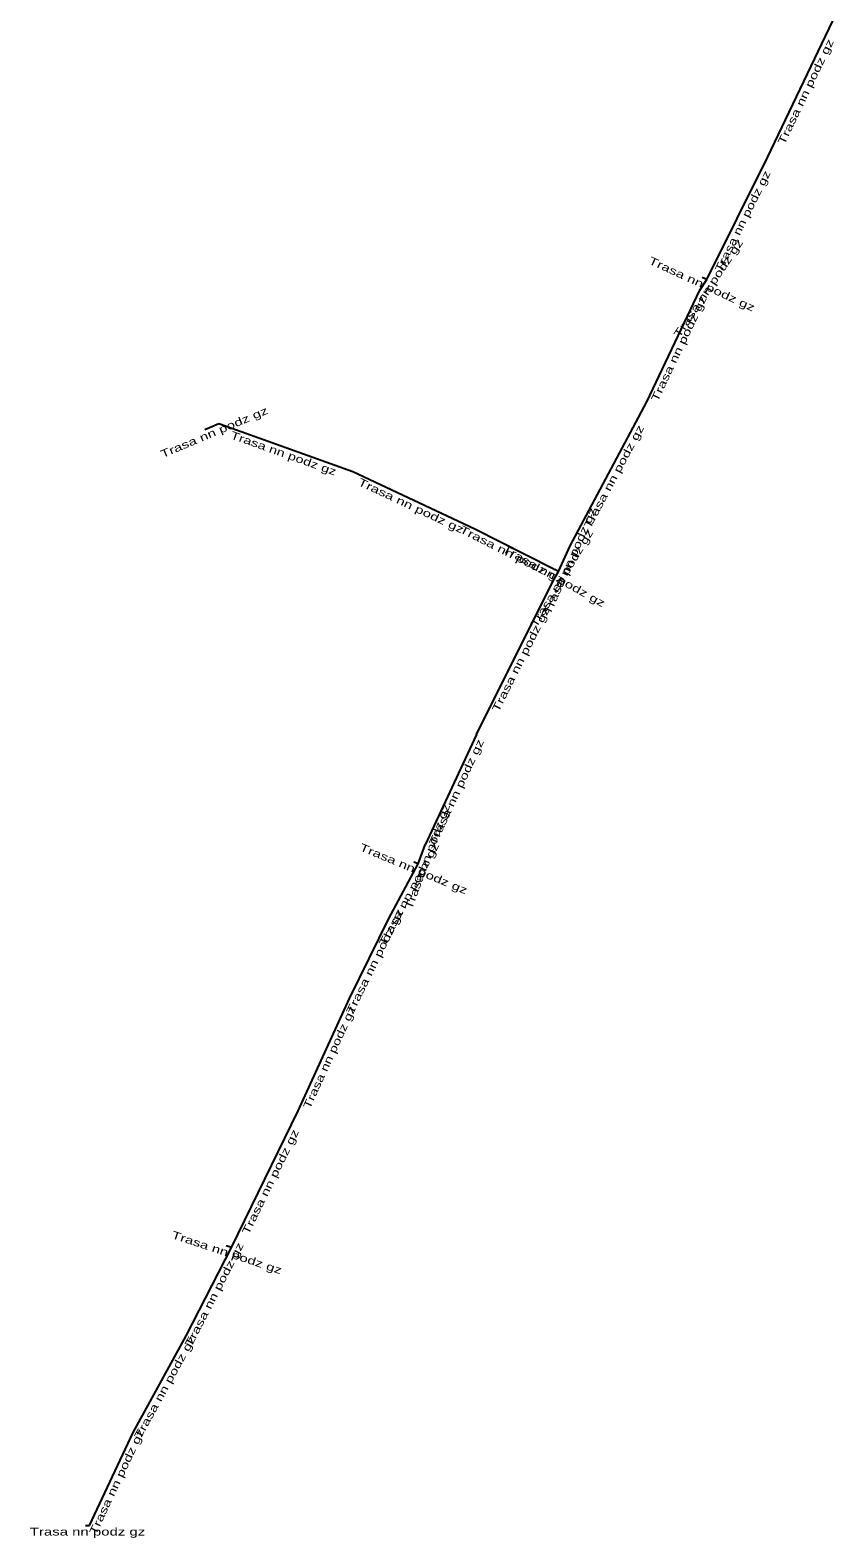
# Model space of a CAD drawing. Extents: x -648599 to -648043, y -1073975 to -1073476.
# Drawn here: x -648541.8 to -648489.6, y -1073846.4 to -1073748.4 of the extents above; entities that cross this region are included whole.
import ezdxf
from ezdxf.enums import TextEntityAlignment as Align

# ---------------------------------------------------------------- set-up
doc = ezdxf.new("R2010")
doc.units = 0
doc.header["$LTSCALE"] = 0.2
doc.layers.add('11', color=7, linetype='Continuous', lineweight=25)
doc.layers.add('20', color=7, linetype='Continuous')

msp = doc.modelspace()

# ---------------------------------------------------------------- linework, layer by layer
at = {"layer": '11'}
for p, q in [((-648493.9, -1073756.69), (-648489.65, -1073747.81)), ((-648497.84, -1073764.62), (-648493.9, -1073756.69)), ((-648501.73, -1073772.56), (-648498.3, -1073765.31)), ((-648498.3, -1073765.31), (-648497.84, -1073764.62)), ((-648497.84, -1073764.62), (-648498.14, -1073764.481)), ((-648506.72, -1073781.92), (-648501.73, -1073772.56)), ((-648530.43, -1073774.36), (-648529.53, -1073773.98)), ((-648529.53, -1073773.98), (-648520.83, -1073777.09)), ((-648520.83, -1073777.09), (-648512.91, -1073780.81)), ((-648507.46, -1073783.59), (-648507.695, -1073783.459)), ((-648512.8, -1073794.17), (-648507.74, -1073784.06)), ((-648512.8, -1073794.17), (-648516.12, -1073801.33)), ((-648516.58, -1073802.58), (-648516.12, -1073801.33)), ((-648518.48, -1073806.13), (-648516.58, -1073802.58)), ((-648516.58, -1073802.58), (-648516.859, -1073802.464)), ((-648521.04, -1073811.33), (-648518.48, -1073806.13)), ((-648524.36, -1073818.61), (-648521.04, -1073811.33)), ((-648528.7, -1073827.49), (-648524.36, -1073818.61)), ((-648531.65, -1073833.24), (-648528.7, -1073827.49)), ((-648528.7, -1073827.49), (-648529.037, -1073827.378)), ((-648535.09, -1073839.51), (-648531.65, -1073833.24)), ((-648537.92, -1073845.55), (-648535.09, -1073839.51)), ((-648538.171, -1073845.55), (-648537.92, -1073845.55))]:
    msp.add_line(p, q, dxfattribs=at)
for points in [[(-648512.91, -1073780.81), (-648507.86, -1073783.368), (-648507.695, -1073783.459)], [(-648507.74, -1073784.06), (-648507.46, -1073783.59), (-648506.72, -1073781.92)]]:
    msp.add_lwpolyline(points, dxfattribs=at)

# ---------------------------------------------------------------- texts
at = {"layer": '20'}
for rotation, width, p in [(64.424, 1.45, (-648491.1877, -1073752.5304)), (63.58, 1.4, (-648495.2873, -1073760.9437)), (56.31, 1.45, (-648497.5284, -1073765.3252)), (335.14, 1.45, (-648498.2626, -1073765.1394)), (64.681, 1.45, (-648499.4262, -1073769.2124)), (22.891, 1.45, (-648529.7267, -1073774.7679)), (61.937, 1.45, (-648503.6509, -1073777.5451)), (340.329, 1.4, (-648525.3987, -1073776.1465)), (334.841, 1.45, (-648517.1458, -1073779.538)), (66.101, 1.45, (-648506.4951, -1073783.0178)), (333.136, 1.45, (-648510.5945, -1073782.7109)), (59.216, 1.4, (-648507.0405, -1073784.1575)), (330.863, 1.45, (-648507.8932, -1073784.092)), (63.412, 1.45, (-648509.688, -1073789.4054)), (65.123, 1.45, (-648513.8694, -1073798.0227)), (69.796, 1.4, (-648515.7395, -1073802.1788)), (337.424, 1.45, (-648516.9685, -1073803.1214)), (61.844, 1.45, (-648516.9565, -1073804.6615)), (63.789, 1.45, (-648519.1758, -1073809.0169)), (65.485, 1.4, (-648522.1081, -1073815.2392)), (63.953, 1.45, (-648525.946, -1073823.3353)), (341.616, 1.45, (-648529.0733, -1073828.0512)), (62.84, 1.45, (-648529.5962, -1073830.6616)), (61.249, 1.45, (-648532.7991, -1073836.6868)), (64.895, 1.45, (-648535.9165, -1073842.8056))]:
    msp.add_text('Trasa nn podz gz', height=0.5, rotation=rotation, dxfattribs=dict(at, width=width)).set_placement(p, align=Align.CENTER)
at = {"layer": '20', "width": 1.45}
msp.add_text('Trasa nn podz gz', height=0.5, dxfattribs=at).set_placement((-648538.0455, -1073846.2), align=Align.CENTER)

doc.saveas('drawing.dxf')
